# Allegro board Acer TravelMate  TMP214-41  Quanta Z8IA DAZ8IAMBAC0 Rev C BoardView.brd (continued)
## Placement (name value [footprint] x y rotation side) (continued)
PR8001  20K_1%_2  [R0201]  53.11 200.28 180 top
PR8002  220K_1%_2  [R0201]  56.84 196.9 180 top
PR8003  20K_1%_2  [R0201]  33.45 102 180 top
PR8004  220K_1%_2  [R0201]  36.06 101.6 90 top
PR8005  10K_1%_2  [R0201]  53.34 198.4 0 top
PR8006  200K_1%_2  [R0201]  34.61 97.29 270 top
PR8007  10K_1%_2  [R0201]  34.69 102 0 top
PR8008  220K_1%_2  [R0201]  55.72 196.9 180 top
PR8009  110K_1%_2  [R0201]  37.22 101.61 270 top
PR8010  *Short_0201  [S0201]  51.56 196.67 180 top
PR8011  *0_5%_4  [R0402]  53.34 197.35 0 top
PR8012  100K_1%_2  [R0201]  48.81 199.06 270 top
PR8013  *Short_0201  [S0201]  48.79 197.33 270 top
PR8014  *Short_0201  [S0201]  33.23 97.66 180 top
PR8015  *Short_0201  [S0201]  39.96 100.3 90 top
PR8016  300K_1%_2  [R0201]  35.67 97.33 270 top
PR8017  100K_1%_2  [R0201]  38.99 100.33 90 top
PR8018  549K_1%_4  [R0402]  56.99 195.91 0 top
PR8019  *0_5%_4  [R0402]  55.24 195.91 180 top
PR8020  *Short_0201  [S0201]  53.51 195.91 0 top
PR8021  76.8K_1%_4  [R0402]  57.35 194.56 90 top
PR8022  47K_1%_2  [R0201]  36.7 119.83 90 top
PR8023  470K_1%_2  [R0201]  81.2 187.58 0 top
PR8024  47K_1%_2  [R0201]  88.79 190.75 90 top
PR8025  *1M_5%_4  [R0402]  59.35 193.19 270 top
PR8026  *Short_0201  [S0201]  58.31 192.99 270 top
PR8027  33K_1%_4  [R0402]  58.36 194.61 270 top
PR8028  220K_1%_2  [R0201]  51.2 191.59 180 top
PR8029  100K_1%_2  [R0201]  57.3 192.96 270 top
PR8030  100K_1%_2  [R0201]  83.76 190.27 270 top
PR8031  470K_1%_2  [R0201]  37.74 119.83 90 top
PR8032  470K_1%_2  [R0201]  89.76 190.24 90 top
PR8033  *Short_0402  [S0402]  25.07 116.76 90 top
PR8034  *Short_0402  [S0402]  17.34 113.77 90 top
PR8035  10K_1%_2  [R0201]  24.51 118.08 180 top
PR8036  18.7K_1%_4  [R0402]  16.98 117.34 90 top
PR8037  *0_5%_4  [R0402]  18.36 113.75 90 top
PR8038  *10K_1%_2  [R0201]  31.77 116.56 90 top
PR8039  10K_1%_4  [R0402]  18.12 118.84 270 top
PR8040  10K_1%_2  [R0201]  23.52 118.08 0 top
PR8041  *Short_0201  [S0201]  31.85 115.08 180 top
PR8042  1M_1%_2  [R0201]  26.16 113.81 0 top
PR8043  1M_1%_2  [R0201]  31.77 117.57 90 top
PR8044  510K_5%_2  [R0201]  22.83 115.47 270 top
PR8045  220K_5%_2  [R0201]  24.38 112.57 180 top
PR8046  1K_1%_2  [R0201]  26.79 116.4 0 top
PR8047  220K_5%_2  [R0201]  26.16 112.57 0 top
PR8048  *1K_1%_2  [R0201]  26.13 115.47 270 top
PR8049  *0_5%_4  [R0402]  28.37 106.45 90 top
PR8050  *0_5%_4  [R0402]  30.88 106.07 270 top
PR8051  *0_5%_4  [R0402]  31.37 107.42 0 top
PR8052  *0_5%_4  [R0402]  36.24 114.32 180 top
PR8053  *27.4K_1%_4  [R0402]  32.14 109.92 90 top
PR8054  *10K_1%_2  [R0201]  33.88 114.2 0 top
PR8055  *10.2K_1%_4  [R0402]  33.14 108.49 270 top
PR8056  *1M_1%_2  [R0201]  24.99 111.55 90 top
PR8057  *10K_1%_2  [R0201]  34.87 114.2 0 top
PR8058  *10K_1%_2  [R0201]  19.86 111.99 270 top
PR8059  *1M_1%_2  [R0201]  27.53 108.56 270 top
PR8060  *0_5%_4  [R0402]  18.56 111.96 0 top
PR8061  *220K_5%_2  [R0201]  27.98 111.97 270 top
PR8062  *220K_5%_2  [R0201]  24.99 110.54 270 top
PR8063  *1K_1%_2  [R0201]  24.84 109.52 180 top
PR8064  *1M_1%_2  [R0201]  19.86 110.99 270 top
PR9000  EV@1_5%_6  [R0603]  94.99 193.37 90 top
PR9001  EV@1_5%_6  [R0603]  105.58 200.05 135 top
PR9002  EV@499K_1%_4  [R0402]  98.57 194.05 0 top
PR9004  *EV@2.2_5%_6  [R0603]  105.61 202.92 315 bottom
PR9006  EV@1_5%_6  [R0603]  98.29 199.06 0 bottom
PR9008  *Short_0201  [S0201]  104.95 194.1 180 top
PR9009  EV@10K_1%_2  [R0201]  104.95 193.39 180 top
PR9011  EV@14.7K_1%_4  [R0402]  102.44 198.05 45 bottom
PR9013  EV@10K_1%_4  [R0402]  104.85 193.49 270 bottom
PR9014  EV@1_5%_6  [R0603]  114.09 191.59 90 bottom
PR9015  *Short_0201  [S0201]  97.79 197.41 0 top
PR9016  *Short_0402  [S0402]  97.06 199.12 180 top
PR9017  *Short_0201  [S0201]  98.67 197.52 270 top
PR9018  *EV@12K_1%_4  [R0402]  97.06 200.08 180 top
PR9019  *EV@2.2_5%_6  [R0603]  105.86 197.48 270 bottom
PR9021  EV@20.5K_1%_4  [R0402]  98.06 194.92 270 bottom
PR9022  *EV@10K_1%_4  [R0402]  98.5 198.9 90 top
PR9023  EV@6.19K_1%_4  [R0402]  97.86 196.55 180 top
PR9024  EV@4.32K_1%_4  [R0402]  96.06 196.54 0 top
PR9025  *EV@0_5%_2  [R0201]  102.66 193.9 45 bottom
PR9026  EV@100_1%_4  [R0402]  116.76 190.4 90 bottom
PR9027  EV@16.5K_1%_4  [R0402]  95.32 195.53 0 top
PR9028  *Short_0201  [S0201]  99.65 191.48 180 top
PR9029  *Short_0201  [S0201]  98.7 192.2 180 top
PR9030  EV@309_1%_4  [R0402]  93.95 195.84 90 top
PR9031  EV@100_1%_4  [R0402]  115.77 190.4 90 bottom
PR9032  EV@14.7K_1%_4  [R0402]  100.88 194.71 45 bottom
PR9033  EV@10K_1%_2  [R0201]  103.42 192.76 315 top
PR9034  *Short_0201  [S0201]  103.17 197.51 225 bottom
PR9067  *Short_0805  [S0805]  97.56 186.08 270 bottom
PR9068  *Short_0805  [S0805]  96.65 183.28 0 bottom
PR9069  *Short_0402  [S0402]  88.69 185.49 270 top
PR9070  EV@0_5%_2  [R0201]  89.45 182.78 180 top
PR9072  EV@0_5%_2  [R0201]  90.06 185.72 0 top
PR9073  EV@5.6_5%_8  [R0805]  95.55 192 180 bottom
PR9074  EV@100K_1%_4  [R0402]  104.95 191.56 90 bottom
PR9075  EV@10K_1%_4  [R0402]  104.56 187.67 0 bottom
PR9076  EV@10K_1%_2  [R0201]  106.34 183.79 0 bottom
PR9077  EV@1M_5%_4  [R0402]  103.93 191.56 270 bottom
PR9078  EV@0_5%_2  [R0201]  105.2 183.79 180 bottom
PR9079  EV@0_5%_2  [R0201]  100.17 181.61 180 bottom
PR9080  EV@47_1%_4  [R0402]  101.09 186.7 180 bottom
PR9081  EV@133_1%_4  [R0402]  99.72 186.97 90 bottom
PR9082  EV@124_1%_4  [R0402]  99.31 184.55 270 bottom
PR9085  *Short_0402  [S0402]  99.35 194.97 90 bottom
PR9086  EV@100K_1%_4  [R0402]  168.56 151.32 0 bottom
PR9087  EV@10_5%_6  [R0603]  168.04 158.17 0 bottom
PR9088  EV@100K_1%_2  [R0201]  168.07 157.68 270 top
PR9089  EV@2.2_5%_6  [R0603]  166.01 158.81 90 bottom
PR9090  EV@0_5%_2  [R0201]  168.19 155.72 270 top
PR9091  *EV@0_5%_2  [R0201]  168.95 156.62 90 top
PR9092  *EV@4.7_5%_6  [R0603]  162.29 158.29 180 top
PR9093  EV@0_5%_2  [R0201]  169.21 155.75 180 top
PR9094  EV@6.49K_1%_4  [R0402]  170.91 151.3 270 bottom
PR9095  EV@2.2K_5%_4  [R0402]  169.41 155.3 180 bottom
PR9096  *EV@0_5%_4  [R0402]  170.28 153.09 0 bottom
PR9097  EV@9.31K_1%_4  [R0402]  168.94 152.7 270 bottom
PR9098  EV@0_5%_4  [R0402]  170.28 153.08 180 top
PR9099  EV@22_5%_8  [R0805]  165.82 168.16 90 top
PR9100  EV@100K_1%_4  [R0402]  160.6 168.55 180 top
PR9101  EV@1M_5%_4  [R0402]  160.98 167.1 90 top
PR9102  EV@1M_5%_6  [R0603]  155.15 168.25 180 top
PR9103  EV@22_5%_8  [R0805]  164.64 209.6 180 top
PR9104  EV@1M_5%_6  [R0603]  155.91 170.35 270 top
PR9105  *EV@100K_1%_6  [R0603]  158.96 209.94 90 top
PR9227  22_5%_8  [R0805]  37.38 125.12 0 top
PR9244  *Short_0805  [S0805]  206.15 126.2 180 bottom
PR9245  *Short_0805  [S0805]  209.67 129.34 0 bottom
PR9248  *Short_0805  [S0805]  37.52 158.86 90 top
PR9249  *Short_0805  [S0805]  32.68 158.77 180 top
PR9255  100K_1%_2  [R0201]  36.62 145.56 0 top
PR9256  *Short_0201  [S0201]  38.1 145.56 270 top
PR9263  *Short_0201  [S0201]  167.56 166.67 0 top
PR9268  *0_5%_2  [R0201]  169.72 135.02 270 bottom
PR9269  *0_5%_2  [R0201]  170.48 135.02 270 bottom
PR9270  *0_5%_2  [R0201]  60.88 182.9 90 bottom
PR9271  *0_5%_2  [R0201]  60.88 183.92 270 bottom
PR9274  *EV@100K_NTC_4_1%  [R0402]  107.54 202.46 90 bottom
PR9275  *Short_0201  [S0201]  163.37 121.18 90 top
PR9276  *Short_0201  [S0201]  160.57 123.03 180 top
PR9277  *0_5%_4  [R0402]  39.37 101.7 0 top
PR9278  *Short_0201  [S0201]  84.25 188.95 180 top
PR9279  *Short_0201  [S0201]  39.09 120.34 180 top
PR9280  *Short_0201  [S0201]  69.41 205.25 90 top
PR9281  *Short_0201  [S0201]  36.14 115.82 270 top
PR9284  *EV@1K_1%_4  [R0402]  99.11 193.19 90 bottom
PR9285  *Short_0201  [S0201]  168.96 135.02 90 bottom
PR9286  22_5%_8  [R0805]  26.08 139.47 0 top
PR9287  *Short_0201  [S0201]  60.12 183.92 90 bottom
PR9288  *Short_0603  [S0603]  87.04 172.36 180 top
PR9289  *100K_1%_2  [R0201]  165.35 149.65 90 bottom
PU1  BQ24780SRUYR  [QFN28-4X4-4-38P]  158.79 119.35 0 bottom
PU3002  TMP708AIDBVR  [SOT23-2_8-95-5P-LP2985-50DBVT]  131.33 116.55 90 bottom
PU3003  *JW5222RSOTB_TRPBF  [SOT23-2_8-95-6P-1_1H]  6.17 34.44 0 bottom
PU3004  JW5213DFND_TRPBF  [DFN8-2X2-5-9P-MAX8902B]  36.75 140.74 180 top
PU5000  G5719CTB1U  [SOT23-6-2_8-95-6P-G5126TB1U]  72.33 186.61 0 bottom
PU5001  RT8231BGQW  [WQFN20-3X3-4-21P]  90.39 176.09 0 top
PU6000  RT6256BGQUF  [QFN12-3X3-45-0_6H]  177.21 130.65 0 bottom
PU6001  AOZ1331ADI  [DFN14-3X2-4-11P-0_8H]  201.13 128.93 90 bottom
PU6002  AOZ1331ADI  [DFN14-3X2-4-11P-0_8H]  35.48 163.34 180 top
PU6003  RT6258CGQUF  [QFN12-3X3-45-0_6H]  55.67 183.08 180 bottom
PU7000  RT3612EBGQW  [QFN32-4X4-4-33P-RT8845B]  159.96 145.87 315 bottom
PU7001  RT6543AGQW  [QFN20-3X3-4-21P-RT6543B]  162.99 134.31 270 bottom
PU8000  AP2204K-ADJTRG1  [SOT23-2_825-95-5P]  20.82 117.7 0 top
PU8001  *AP2204K-ADJTRG1  [SOT23-2_825-95-5P]  35.4 110.66 90 top
PU9000  EV@RT8813DGQW  [QFN24-4X4-5-25P-RT8813D]  101.99 195.99 225 top
PU9002  EV@AOZ1331ADI  [DFN14-3X2-4-11P-0_8H]  94.41 184.17 270 top
PU9003  EV@G9336ADJTP1U  [TSOT23-6-2_8-95-6P-1H]  102.36 184.57 0 bottom
PU9004  EV@G5335QT2U  [QFN23-4X4-5-25P]  165.53 154.41 270 bottom
PU9005  *M74VHC1GT08DFT2G  [SC70-2_1-65-5P]  31.92 140.1 90 top
PU9006  *MC74VHC1G08DFT2G  [SOT353-1-2_125-65-5P]  166.75 147.67 270 bottom
Q9  EV@PJA138K  [SOT23-2-95-3P]  112.31 188.41 90 bottom
Q13  EV@PJX138K  [SOT563-1_6-5-6P-PJX138K]  134.79 175.92 0 bottom
Q14  EV@DMG1012T-7  [SOT23-1_38-5-3P]  110.87 186.36 90 top
Q15  *EV@DMG1012T-7  [SOT23-1_38-5-3P]  106.17 182.22 180 bottom
Q16  EV@DMG1012T-7  [SOT23-1_38-5-3P]  112.19 188.87 180 top
Q20  EV@DMG1012T-7  [SOT23-1_38-5-3P]  162.2 190.5 0 top
Q21  *PJA138K  [SOT23-2-95-3P]  32.81 29.08 180 bottom
Q22  2N7002KTB  [SOT23-1_38-5-3P]  78.91 102.89 180 top
Q23  DMP2130L-7  [SOT23-2-95-3P]  29.63 175.3 270 top
Q28  METR3904-G  [SOT23-2-95-3P]  5.12 12.46 180 top
Q30  DMP2130L-7  [SOT23-2-95-3P]  216.48 122.32 180 bottom
Q31  DDTC144EUA-7-F  [SOT23-1_7-65-3P]  214.17 119.4 270 bottom
Q32  DMP2130L-7  [SOT23-2-95-3P]  114.32 107.87 90 bottom
Q33  *2N7002KTB  [SOT23-1_38-5-3P]  185.59 111.91 0 top
Q62  SSM6N43FU  [SC70-2_1-65-6P]  25.45 135.66 0 top
Q63  2N7002KTB  [SOT23-1_38-5-3P]  185.59 109.37 90 top
Q81  PJA138K  [SOT23-2-95-3P]  13.63 147.34 0 bottom
Q85  DMG301NU-7  [SOT23-2-95-3P]  109.39 107.21 180 top
Q86  METR3904-G  [SOT23-2-95-3P]  105.46 104.26 180 top
Q124  *METR3904-G  [SOT23-2-95-3P]  54.83 136.88 0 top
Q6508  G5250Q1T73U  [SOT23-2_38-95-3P]  17.04 134.18 180 top
Q6509  2N7002K  [SOT23-2-95-3P]  142.29 96.75 90 top
Q6512  EV@2N7002KTB  [SOT23-1_38-5-3P]  130.98 176.04 270 bottom
Q6520  *2N7002KTB  [SOT23-1_38-5-3P]  78.79 106.07 270 top
Q6521  2N7002KDW  [SOT363-2_1-65-6P]  86.52 189.22 0 bottom
Q6522  DDTC144EUA-7-F  [SOT23-1_7-65-3P]  81.83 190.14 270 bottom
Q6523  METR3904-G  [SOT23-2-95-3P]  164.41 123.59 180 bottom
Q6531  2N7002K  [SOT23-2-95-3P]  25.7 159.79 270 top
Q6534  CRT@G5250Q1T73U  [SOT23-2_38-95-3P]  19.03 150.29 180 top
Q6540  SPIN_EXT@2N7002K  [SOT23-2-95-3P]  131.86 213.36 90 top
Q6544  METR3904-G  [SOT23-2-95-3P]  140.83 159.7 180 top
Q6554  I219@2N7002KDW  [SOT363-2_1-65-6P]  11.6 167.28 0 top
Q6555  NFC@2N7002KTB  [SOT23-1_38-5-3P]  59.66 94.51 90 top
Q6556  NFC@2N7002KTB  [SOT23-1_38-5-3P]  64.31 94.51 90 top
Q6557  NFC@2N7002KTB  [SOT23-1_38-5-3P]  66.59 94.51 90 top
Q6558  NFC@2N7002KTB  [SOT23-1_38-5-3P]  69.9 94.38 90 top
Q6559  NFC@2N7002KTB  [SOT23-1_38-5-3P]  61.87 94.64 270 top
Q6564  2N7002KDW  [SOT363-2_1-65-6P]  93.77 182.65 270 bottom
Q6565  2N7002K  [SOT23-2-95-3P]  30.68 52.3 270 bottom
Q6567  **SPIN_INT@2N7002KDW  [SOT363-2_1-65-6P]  150.79 215.8 0 top
Q6570  2N7002K  [SOT23-2-95-3P]  32.68 56.92 270 bottom
Q6582  METR3904-G  [SOT23-2-95-3P]  83.1 169.95 270 top
Q6583  2N7002KTB  [SOT23-1_38-5-3P]  87.17 169.06 270 top
Q6585  *2N7002KDW  [SOT363-2_1-65-6P]  77.9 119.78 90 top
Q6588  2N7002KTB  [SOT23-1_38-5-3P]  91.96 107.08 180 top
Q6589  METR3904-G  [SOT23-2-95-3P]  88.97 107.59 180 top
Q6591  TSN@DMP2130L-7  [SOT23-2-95-3P]  74.72 186.59 0 top
Q6592  TSN@DDTC144EUA-7-F  [SOT23-1_7-65-3P]  77.9 187.55 0 top
Q6593  2N7002K  [SOT23-2-95-3P]  6.12 42.57 90 bottom
Q6597  *2N7002KDW  [SOT363-2_1-65-6P]  161.08 140.36 270 top
Q6598  *2N7002KDW  [SOT363-2_1-65-6P]  163.55 140.36 270 top
Q6600  *DMP2130L-7  [SOT23-2-95-3P]  200.58 116.1 0 bottom
Q6601  **2N7002KDW  [SOT363-2_1-65-6P]  205.02 118.13 180 bottom
Q6602  2N7002KTB  [SOT23-1_38-5-3P]  14.27 59.33 90 bottom
Q6603  2N7002KTB  [SOT23-1_38-5-3P]  26.59 47.7 0 bottom
Q6604  SM@DMP2130L-7  [SOT23-2-95-3P]  228.39 93.75 0 top
Q6605  SM@DDTC144EUA-7-F  [SOT23-1_7-65-3P]  234.49 95.91 90 top
Q6606  *EX-IO@2N7002KDW  [SOT363-2_1-65-6P]  137.33 128.6 0 bottom
Q6607  DMG3414U-7  [SOT23-2-95-3P]  209.21 121.31 270 bottom
Q6608  2N7002KDW  [SOT363-2_1-65-6P]  202.36 120.8 90 top
Q6609  EMF11N02J  [SOT23-2_38-95-3P]  169.08 139.85 180 bottom
Q6610  2N7002K  [SOT23-2-95-3P]  170.48 148.74 90 bottom
Q6611  DDTC144EUA-7-F  [SOT23-1_7-65-3P]  170.48 150.9 270 top
Q6612  *PJA138K  [SOT23-2-95-3P]  18.84 73.94 0 top
Q6616  *2N7002KDW  [SOT363-2_1-65-6P]  73.71 94 0 top
Q6617  2N7002K  [SOT23-2-95-3P]  8.2 56.79 0 bottom
Q6618  2N7002K  [SOT23-2-95-3P]  29.13 160.8 0 top
Q6619  I219@2N7002K  [SOT23-2-95-3P]  31.92 165.63 180 top
Q6620  2N7002K  [SOT23-2-95-3P]  11.35 163.22 0 top
Q6621  *2N7002KTB  [SOT23-1_38-5-3P]  10 43.08 270 bottom
Q6622  2N7002KTB  [SOT23-1_38-5-3P]  26.59 54.51 0 bottom
Q6623  *2N7002KTB  [SOT23-1_38-5-3P]  10 45.62 270 bottom
Q6624  2N7002KTB  [SOT23-1_38-5-3P]  26.59 52.22 0 bottom
Q6625  2N7002KTB  [SOT23-1_38-5-3P]  26.59 49.93 0 bottom
Q6626  *2N7002KTB  [SOT23-1_38-5-3P]  20.77 42.01 180 bottom
Q6627  *2N7002KTB  [SOT23-1_38-5-3P]  18.41 41.65 270 bottom
Q6628  *2N7002KTB  [SOT23-1_38-5-3P]  16.17 41.07 270 bottom
Q6629  *2N7002KTB  [SOT23-1_38-5-3P]  13.97 41.07 270 bottom
Q6631  SPIN_EXT@2N7002KDW  [SOT363-2_1-65-6P]  147.87 210.72 270 bottom
Q6632  SPIN_EXT@2N7002K  [SOT23-2-95-3P]  102.66 181 270 bottom
Q6633  SPIN_EXT@2N7002K  [SOT23-2-95-3P]  106.09 178.3 270 bottom
Q6637  **SPIN_INT@2N7002K  [SOT23-2-95-3P]  144.83 210.59 0 top
Q6638  *SPIN_INT@2N7002KDW  [SOT363-2_1-65-6P]  126.41 113.31 270 bottom
Q6639  *METR3904-G  [SOT23-2-95-3P]  53.39 140.36 90 top
Q6640  *METR3904-G  [SOT23-2-95-3P]  91.79 178.74 270 bottom
Q6642  *HDD_MS@AO3413  [SOT23-2_38-95-3P]  233.34 123.21 90 top
Q6643  *HDD_MS@2N7002K  [SOT23-2-95-3P]  229.66 125.5 90 top
Q6644  *HDD_MS@AO3413  [SOT23-2_38-95-3P]  216.2 107.72 270 top
Q6645  *HDD_MS@2N7002K  [SOT23-2-95-3P]  213.41 104.54 270 top
Q6646  *2N7002K  [SOT23-2-95-3P]  59.69 175.16 90 top
Q6649  2N7002KTB  [SOT23-1_38-5-3P]  105.96 109.5 180 bottom
Q6651  PJX138K  [SOT563-1_6-5-6P-PJX138K]  138.48 98.96 90 top
Q6652  EV@2N7002KTB  [SOT23-1_38-5-3P]  116.05 180.69 180 top
Q6653  **SPIN_INT@2N7002K  [SOT23-2-95-3P]  51.23 195.09 270 bottom
Q6654  PJA138K  [SOT23-2-95-3P]  88.62 126.34 180 top
Q6655  *SSD_MS@AO3413  [SOT23-2_38-95-3P]  20.65 77.37 90 top
Q6656  *SSD_MS@2N7002K  [SOT23-2-95-3P]  24.43 81.68 90 top
Q6657  *DDTC144EUA-7-F  [SOT23-1_7-65-3P]  63.11 175 0 top
QG15  EV@DMG1012T-7  [SOT23-1_38-5-3P]  111.45 179.24 270 bottom
QG17  *EV@PJX138K  [SOT563-1_6-5-6P-PJX138K]  113.03 176.83 90 bottom
R36  4.7K_1%_2  [R0201]  92.25 120.67 180 top
R61  *CRT@0_4/S  [S0402]  35.61 146.45 270 top
R101  4.7K_1%_2  [R0201]  138.35 100.48 0 top
R224  240_1%_2  [R0201]  46.4 137.44 270 top
R225  *0_5%_4  [R0402]  45.13 108.23 180 top
R226  *0_5%_4  [R0402]  45.13 106.19 180 top
R227  *0_5%_4  [R0402]  44.67 128.11 180 top
R228  *0_4/S  [S0402]  45.13 107.21 0 top
R229  *0_4/S  [S0402]  45.13 105.18 180 top
R230  *0_4/S  [S0402]  45.01 129.48 270 top
R231  240_1%_2  [R0201]  49.91 148.48 180 top
R232  240_1%_2  [R0201]  49.92 147.74 180 top
R233  *240_1%_2  [R0201]  47.18 149.02 180 top
R234  *240_1%_2  [R0201]  49.9 149.97 0 top
R235  *240_1%_2  [R0201]  52.3 147.25 180 top
R236  *240_1%_2  [R0201]  52.35 145.85 180 top
R237  *240_1%_2  [R0201]  47.29 149.78 180 top
R238  *240_1%_2  [R0201]  49.92 149.22 0 top
R239  *240_1%_2  [R0201]  47.72 146.79 180 top
R240  *240_1%_2  [R0201]  47.85 145.97 180 top
R241  1K_1%_2  [R0201]  45.98 124.37 180 top
R242  2_1%_6  [R0603]  45.25 121.87 270 top
R243  1K_1%_2  [R0201]  46.02 126.05 0 top
R244  24.9_1%_2  [R0201]  45.51 118.26 180 top
R296  *EV@0_4/S  [S0402]  120.19 207.92 180 bottom
R297  EV@10K_1%_2  [R0201]  115.54 188.36 270 bottom
R299  *EV@0_4/S  [S0402]  126.81 198.36 90 top
R305  *EV@0_4/S  [S0402]  110.76 185.54 90 bottom
R306  EV@100K_1%_2  [R0201]  110.51 186.81 0 bottom
R307  *EV@200_1%_2  [R0201]  141.24 207.26 180 bottom
R310  4.7K_1%_2  [R0201]  7.51 13.51 180 top
R311  EV@10K_1%_2  [R0201]  121.84 208.81 90 bottom
R312  EV@2.49K_1%_2  [R0201]  142.9 207.11 180 bottom
R313  EV@10K_1%_2  [R0201]  116.07 187.4 180 bottom
R314  EV@10K_1%_2  [R0201]  145.08 189.76 90 bottom
R315  EV@10K_1%_2  [R0201]  145.59 188.49 180 bottom
R316  EV@10K_1%_2  [R0201]  146.22 187.47 180 bottom
R317  EV@10K_1%_2  [R0201]  159.81 204.49 0 top
R318  EV@40.2_1%_2  [R0201]  146.98 181.76 180 top
R319  EV@40.2_1%_2  [R0201]  146.41 182.97 270 top
R320  EV@60.4_1%_2  [R0201]  146.47 183.51 0 bottom
R321  *EV@60.4_1%_2  [R0201]  136.41 186.63 0 top
R322  *EV@60.4_1%_2  [R0201]  136.75 189.43 270 top
R323  *EV@0_5%_4  [R0402]  124.92 208.77 180 bottom
R324  *EV@0_4/S  [S0402]  124.92 209.78 180 bottom
R325  EV@100K_1%_2  [R0201]  128.06 208.68 90 bottom
R326  EV@10K_1%_2  [R0201]  118.46 177.64 270 bottom
R329  *EV@0_4/S  [S0402]  124.67 192.21 270 top
R330  *EV@10K_1%_2  [R0201]  123.49 176.43 270 bottom
R331  EV@10K_1%_2  [R0201]  124.89 178.46 270 bottom
R332  EV@10K_1%_2  [R0201]  124.12 178.46 270 bottom
R338  100K_1%_2  [R0201]  91.84 122.22 270 top
R339  *EV@0_4/S  [S0402]  134.41 178.33 0 bottom
R341  EV@100K_1%_2  [R0201]  131.85 177.8 270 bottom
R342  EV@100K_1%_2  [R0201]  130.3 178.18 270 bottom
R343  EV@100K_1%_2  [R0201]  132.89 178.33 0 bottom
R344  XX@100K_1%_2  [R0201]  114.22 185.95 180 bottom
R345  XX@100K_1%_2  [R0201]  114.22 184.93 180 bottom
R346  XX@100K_1%_2  [R0201]  114.22 183.16 180 bottom
R347  *EV@100K_1%_2  [R0201]  114.22 186.79 180 bottom
R348  *EV@100K_1%_2  [R0201]  114.22 182.39 180 bottom
R349  *EV@100K_1%_2  [R0201]  114.12 183.92 180 bottom
R350  *EV@30.1K_1%_4  [R0402]  131.46 179.19 0 bottom
R351  *EV@100K_1%_2  [R0201]  132.89 179.22 0 bottom
R352  EV@100K_1%_2  [R0201]  129.43 178.46 0 bottom
R353  XX@100K_1%_2  [R0201]  116.5 185.57 0 bottom
R354  XX@100K_1%_2  [R0201]  116.5 184.43 180 bottom
R355  XX@100K_1%_2  [R0201]  116.5 182.65 0 bottom
R356  EV@100K_1%_2  [R0201]  116.5 186.59 0 bottom
R357  EV@100K_1%_2  [R0201]  116.5 181.89 0 bottom
R358  EV@100K_1%_2  [R0201]  116.5 183.54 0 bottom
R359  *0_5%_4  [R0402]  169.34 114.83 0 top
R361  4.7K_1%_2  [R0201]  162 113.18 90 top
R362  EV@4.7K_1%_2  [R0201]  137.21 175.44 180 bottom
R363  EV@2.2K_5%_2  [R0201]  123.16 178.46 270 bottom
R364  *EV@0_4/S  [S0402]  122.6 176.43 90 bottom
R365  EV@4.7K_1%_2  [R0201]  132.5 175.31 270 bottom
R366  EV@2.2K_5%_2  [R0201]  122.35 178.46 270 bottom
R367  EV@2.2K_5%_2  [R0201]  121.58 178.46 270 bottom
R368  EV@2.2K_5%_2  [R0201]  120.82 178.46 270 bottom
R369  4.7K_1%_2  [R0201]  161.26 113.18 90 top
R370  *EV@0_4/S  [S0402]  116.25 179.73 0 bottom
R372  *EV@0_4/S  [S0402]  114.53 186.89 270 top
R373  *EV@0_4/S  [S0402]  115.23 184.68 0 top
R374  *EV@0_4/S  [S0402]  116.17 183.03 0 top
R376  *EV@0_4/S  [S0402]  116.25 180.74 0 bottom
R378  *EV@10K_1%_2  [R0201]  129.51 176.55 90 bottom
R380  43_5%_2  [R0201]  159.3 114.7 0 top
R382  *EV@0_5%_4  [R0402]  105.84 180.62 180 bottom
R383  4.7K_1%_2  [R0201]  146.98 109.62 0 top
R384  *EV@0_4/S  [S0402]  108 180.87 0 bottom
R385  *EV@4.7K_1%_2  [R0201]  108.76 182.27 0 bottom
R386  EV@10K_1%_2  [R0201]  113.33 187.35 0 top
R391  EV@10K_1%_2  [R0201]  113.96 180.87 180 bottom
R394  EV@10K_1%_2  [R0201]  115.11 188.36 0 top
R395  EV@10K_1%_2  [R0201]  116.84 178.71 270 bottom
R396  EV@10K_1%_2  [R0201]  115.57 205.89 180 bottom
R397  EV@10K_1%_2  [R0201]  114.35 183.28 180 top
R398  EV@100K_1%_2  [R0201]  124.69 187.15 270 top
R399  *EV@10K_1%_2  [R0201]  113.96 179.85 180 bottom
R402  *22_5%_2  [R0201]  149.6 104.85 0 top
R403  EV@10K_1%_2  [R0201]  114.22 182.39 270 top
R404  EV@10K_1%_2  [R0201]  114.22 181.63 180 bottom
R405  EV@120_1%_2  [R0201]  158.77 187.07 270 bottom
R406  EV@120_1%_2  [R0201]  158.39 191.77 0 bottom
R407  EV@549_1%_2  [R0201]  159.91 189.48 180 top
R409  100K_1%_2  [R0201]  79.04 104.42 180 top
R410  EV@1.33K_1%_2  [R0201]  159.91 188.46 0 top
R411  EV@931_1%_2  [R0201]  159.91 190.5 0 top
R414  20K_1%_2  [R0201]  24.3 97.81 90 top
R415  39K_1%_2  [R0201]  22.4 97.05 90 top
R416  100K_1%_2  [R0201]  18.44 100.96 90 top
R417  10K_1%_2  [R0201]  16.1 97.3 270 top
R418  10K_1%_2  [R0201]  16.35 99.01 0 top
R421  *0_4/S  [S0402]  20.49 89.81 180 top
R422  *0_4/S  [S0402]  20.51 90.82 180 top
R424  *0_4/S  [S0402]  23.21 91.21 90 top
R425  *0_4/S  [S0402]  19.63 103.4 180 top
R426  *0_4/S  [S0402]  19.63 104.42 180 top
R427  *0_4/S  [S0402]  22.94 105.2 180 top
R428  *0_4/S  [S0402]  22.94 106.4 180 top
R429  *0_4/S  [S0402]  24.23 107.36 180 top
R430  *0_4/S  [S0402]  24.23 108.56 180 top
R432  *0_4/S  [S0402]  24.18 91.21 90 top
R436  *0_4/S  [S0402]  69.96 188.7 180 bottom
R439  *1K_1%_2  [R0201]  64.56 188.24 270 bottom
R440  *1K_1%_2  [R0201]  83.48 192.15 270 bottom
R441  1K_1%_2  [R0201]  66.34 188.24 90 bottom
R442  100K_1%_2  [R0201]  67.61 188.49 90 bottom
R443  10_5%_2  [R0201]  65.58 188.24 270 bottom
R445  *0_4/S  [S0402]  78.48 194.72 180 top
R446  100K_1%_2  [R0201]  78.48 193.67 90 top
R447  100K_1%_2  [R0201]  16.68 27.58 90 top
R449  *0_5%_4  [R0402]  12.62 37.66 180 bottom
R450  *0_6/S  [S0603]  18.82 25.54 90 bottom
R451  200K_1%_2  [R0201]  23.03 27.58 270 bottom
R452  100K_1%_2  [R0201]  24.3 27.71 0 bottom
R454  *0_5%_4  [R0402]  24.68 37.23 90 bottom
R455  *Short_0603  [S0603]  26.59 37.13 0 bottom
R458  *CRT@4.7K_1%_2  [R0201]  31.8 148.1 90 top
R459  *0_4/S  [S0402]  28.49 36.34 270 bottom
R460  *0_5%_4  [R0402]  28.11 28.22 90 bottom
R461  22_5%_2  [R0201]  26.23 34 180 bottom
R462  *Short_0603  [S0603]  29.33 28.06 90 bottom
R463  *0_4/S  [S0402]  13.13 36.47 180 bottom
R464  *0_5%_4  [R0402]  19.09 18.81 135 bottom
R465  *0_5%_4  [R0402]  21.51 21.04 135 top
R467  *0_4/S  [S0402]  13.13 33.55 180 bottom
R468  2.2K_5%_2  [R0201]  19.63 25.12 90 top
R469  *0_5%_4  [R0402]  18 38.63 270 bottom
R470  *0_4/S  [S0402]  19.09 18.81 315 top
R471  2.2K_5%_2  [R0201]  20.37 25.12 90 top
R472  62_1%_2  [R0201]  15.77 21.56 0 bottom
R473  62_1%_2  [R0201]  10.78 28.48 90 bottom
R474  *10K_1%_2  [R0201]  17.14 21.21 270 bottom
R475  *10K_1%_2  [R0201]  18.16 22.14 270 bottom
R476  4.7K_1%_2  [R0201]  17.01 22.62 270 bottom
R477  4.7K_1%_2  [R0201]  18.29 23.39 180 bottom
R478  1K_1%_2  [R0201]  23.1 37.1 90 bottom
R479  *10K_1%_2  [R0201]  30.4 34.06 90 bottom
R490  2.2K_5%_2  [R0201]  16.17 131.21 270 top
R491  2.2K_5%_2  [R0201]  16.17 130.07 90 top
R495  *HDD@4.7K_1%_2  [R0201]  235.38 115.85 0 top
R497  HDD@4.7K_1%_2  [R0201]  233.85 115.08 180 top
R498  *HDD@4.7K_1%_2  [R0201]  235.38 115.08 0 top
R499  *HDD@4.7K_1%_2  [R0201]  233.85 114.27 180 top
R500  HDD@4.7K_1%_2  [R0201]  235.38 114.27 0 top
R503  *HDD@4.7K_1%_2  [R0201]  225.17 114.8 180 top
R504  HDD@4.7K_1%_2  [R0201]  226.69 115.74 0 top
R505  *HDD@4.7K_1%_2  [R0201]  225.17 115.74 180 top
R506  *HDD@4.7K_1%_2  [R0201]  226.69 117.67 0 top
R509  8111K@1K_1%_2  [R0201]  29 157.91 180 top
R510  8111K@15K_1%_2  [R0201]  23.67 161.57 0 top
R511  *0_4/S  [S0402]  29.38 169.06 180 top
R512  *0_4/S  [S0402]  29.38 170.08 180 top
R516  75_1%_8  [R0805]  38.15 184.81 270 top
R517  75_1%_8  [R0805]  35.86 184.81 270 top
R518  75_1%_8  [R0805]  32.56 184.81 270 top
R519  75_1%_8  [R0805]  30.27 184.81 270 top
R558  *0_4/S  [S0402]  127.68 99.72 180 top
R560  *0_4/S  [S0402]  129.59 99.72 0 top
R566  4.7K_1%_2  [R0201]  135.3 97.43 90 top
R567  4.7K_1%_2  [R0201]  130.31 96.19 180 top
R572  *0_4/S  [S0402]  126.24 96.65 90 top
R573  *0_4/S  [S0402]  133.45 103.2 0 bottom
R574  *10K_1%_2  [R0201]  127.25 96.65 90 top
R575  *Short_0603  [S0603]  171.23 111.5 180 bottom
R576  1K_1%_2  [R0201]  166 124.71 90 bottom
R579  10K_1%_2  [R0201]  214.17 121.64 270 bottom
R580  10K_1%_2  [R0201]  83.87 99.72 270 top
R583  10K_1%_2  [R0201]  82.72 97.43 90 top
R586  10K_1%_2  [R0201]  82.72 98.45 270 top
R588  *0_5%_4  [R0402]  23.55 25.17 135 top
R589  *0_5%_4  [R0402]  17.55 17.37 135 top
R592  *0_5%_2  [R0201]  82.47 94.89 270 top
R593  *0_2/S  [S0201]  84.48 100.99 270 top
R600  *1.2K_5%_2  [R0201]  92.38 97.81 180 top
R601  *0_2/S  [S0201]  87.73 102 180 top
R608  *0_5%_4  [R0402]  114.85 110.26 0 bottom
R609  10K_1%_2  [R0201]  112.82 104.75 180 bottom
R614  *Short_0603  [S0603]  119.17 99.26 90 bottom
R646  *SSD@0_2/S  [S0201]  23.67 82.57 270 bottom
R647  *SSD@0_2/S  [S0201]  24.43 82.57 270 bottom
R651  100K_1%_2  [R0201]  183.94 111.02 270 top
R652  4.7K_1%_2  [R0201]  183.94 109.88 90 top
R665  49.9_1%_2  [R0201]  194.61 116.61 270 bottom
R667  49.9_1%_2  [R0201]  194.61 115.59 0 bottom
R670  *0_4/S  [S0402]  194.99 110.77 180 bottom
R671  *10K_1%_2  [R0201]  194.48 108.48 270 bottom
R672  *10K_1%_2  [R0201]  194.48 107.34 270 bottom
R676  *75K_1%_2  [R0201]  190.67 118.64 180 top
R678  *75K_1%_2  [R0201]  186.35 119.02 180 top
R720  33_1%_2  [R0201]  195.24 98.83 90 top
R732  *100K_1%_2  [R0201]  28.87 33.55 0 bottom
R734  10K_1%_2  [R0201]  26.33 28.47 180 bottom
R735  *0_2/S  [S0201]  26.46 24.91 90 bottom
R736  *0_4/S  [S0402]  24.28 26.5 0 top
R738  *0_4/S  [S0402]  26.87 30.32 0 bottom
R752  6.2K_1%_2  [R0201]  26.72 64.67 270 bottom
R753  *Short_0603  [S0603]  27.1 67.59 90 bottom
R803  CRT@75_1%_2  [R0201]  25.24 151.09 180 top
R821  1K_1%_2  [R0201]  107.11 106.32 270 top
R822  1K_1%_2  [R0201]  107.49 103.15 90 top
R825  *100K_1%_2  [R0201]  111.3 108.61 270 top
R849  CRT@75_1%_2  [R0201]  24.03 152.66 270 top
R850  CRT@75_1%_2  [R0201]  23.48 154.54 90 top
R890  100K_1%_2  [R0201]  149.27 96.03 180 top
R894  *0_2/S  [S0201]  148.31 100.28 90 top
R895  33_1%_2  [R0201]  169.59 113.18 0 top
R953  1K_1%_2  [R0201]  77.52 96.03 90 top
R956  33_1%_2  [R0201]  170.96 103.17 270 top
R960  33_1%_2  [R0201]  169.31 104.95 90 top
R971  20K_1%_2  [R0201]  77.39 104.54 90 top
R978  *0_4/S  [S0402]  78.53 96.29 270 top
R979  20K_1%_2  [R0201]  79.17 101.24 90 top
R1234  HDD@4.7K_1%_2  [R0201]  233.85 116.35 180 top
R1235  HDD@4.7K_1%_2  [R0201]  226.69 114.8 0 top
R1236  *HDD@4.7K_1%_2  [R0201]  226.69 116.68 0 top
R1237  HDD@4.7K_1%_2  [R0201]  225.17 117.67 180 top
R1238  HDD@4.7K_1%_2  [R0201]  225.17 116.68 180 top
R1239  *HDD@Short_0603  [S0603]  235.25 118.89 90 top
R1250  20K_1%_2  [R0201]  16.3 134.72 0 bottom
R1616  *CRT@4.7K_1%_2  [R0201]  30.78 148.1 90 top
R1684  *10K_1%_2  [R0201]  57.65 136.32 180 top
R2652  *SSD@0_2/S  [S0201]  34.19 82.57 270 bottom
R2653  *SSD@0_2/S  [S0201]  33.43 82.57 270 bottom
R2654  *SSD@0_2/S  [S0201]  30.66 82.55 270 bottom
R2655  *SSD@0_2/S  [S0201]  29.9 82.55 270 bottom
R2656  *SSD@0_2/S  [S0201]  27.49 82.55 270 bottom
R2657  *SSD@0_2/S  [S0201]  26.75 82.55 270 bottom
R2658  *SSD@0_2/S  [S0201]  21.49 82.5 270 bottom
R2659  *SSD@0_2/S  [S0201]  20.73 82.5 270 bottom
R2661  *SSD@Short_0603  [S0603]  29.26 70.25 0 bottom
R2665  *0_2/S  [S0201]  194.86 109.5 0 bottom
R2666  *0_5%_8  [R0805]  196.39 120.04 90 bottom
R2667  *Short_0603  [S0603]  194.36 120.04 90 bottom
R4008  I219@1K_1%_2  [R0201]  14.02 166.9 180 top
R4009  I219@3.01K_1%_2  [R0201]  26.21 171.47 0 top
R4023  I219@499_1%_2  [R0201]  15.03 168.81 0 top
R4024  I219@499_1%_2  [R0201]  14 165.99 0 top
R9340  I219@4.7K_1%_2  [R0201]  29 158.65 0 top
R25270  *100K_1%_2  [R0201]  67.94 191.03 270 top
R25271  *100K_1%_2  [R0201]  67.13 191.03 270 top
R25282  EV@1.33K_1%_2  [R0201]  158.64 193.85 180 top
R25283  EV@931_1%_2  [R0201]  160.42 192.53 0 top
R25284  EV@549_1%_2  [R0201]  160.42 193.8 180 top
R25288  *Short_0402  [S0402]  59.99 189.89 270 bottom
R25289  *Short_0402  [S0402]  61.01 189.89 270 bottom
R25295  *Short_0402  [S0402]  114.85 105.05 180 top
R25297  *0_4/S  [S0402]  16.52 132.81 0 bottom
R25298  100K_1%_2  [R0201]  144.44 97.3 90 top
R25300  100K_1%_2  [R0201]  145.33 101.67 180 top
R25303  *10K_1%_2  [R0201]  165.73 113.43 90 top
R25304  4.7K_1%_2  [R0201]  146.12 108.3 0 top
R25306  2.2_5%_6  [R0603]  170.43 109.98 90 top
R25307  *2.2_5%_6  [R0603]  144.8 106.4 90 top
R25308  33_1%_2  [R0201]  149.65 110.92 90 top
R25309  10K_1%_2  [R0201]  167 113.18 90 top
R25310  100K_1%_2  [R0201]  69.13 181 90 bottom
R25311  100K_1%_2  [R0201]  170.35 97.43 90 top
R25312  10K_1%_2  [R0201]  144.32 100.61 90 top
R25314  10K_1%_2  [R0201]  162.81 113.18 90 top
R25315  33_1%_2  [R0201]  162.28 115.47 90 top
R25316  *10K_1%_2  [R0201]  164.99 113.43 90 top
R25317  2.2_5%_6  [R0603]  146.22 106.4 90 top
R25318  33_1%_2  [R0201]  169.08 95.02 0 top
R25320  100K_1%_2  [R0201]  155.2 113.05 90 top
R25321  *Short_0402  [S0402]  14.14 155.6 0 bottom
R25322  EV@10K_1%_2  [R0201]  129.51 175.41 90 bottom
R25323  *10K_1%_2  [R0201]  148.89 110.92 270 top
R25330  *0_4/S  [S0402]  167.94 115.08 90 top
R25344  *Short_0603  [S0603]  94.79 99.97 270 top
R25346  *0_5%_6  [R0603]  94.79 102.64 90 top
R25347  *Short_0603  [S0603]  94.84 96.68 270 top
R25348  *0_5%_6  [R0603]  96.37 96.68 270 top
R25365  *0_4/S  [S0402]  84.17 188.9 0 bottom
R25366  *0_4/S  [S0402]  84.02 191.13 180 bottom
R25367  10K_1%_2  [R0201]  82.21 192.3 0 bottom
R25368  10K_1%_2  [R0201]  88.69 189.38 0 bottom
R25369  100K_1%_2  [R0201]  83.87 190.01 180 bottom
R25370  *100K_1%_2  [R0201]  88.69 190.4 180 bottom
R25371  22K_5%_2  [R0201]  26.46 26.18 270 bottom
R25372  10K_1%_2  [R0201]  182.42 121.18 270 bottom
R25373  10K_1%_2  [R0201]  168.83 123.47 90 bottom
R25445  10K_1%_2  [R0201]  23.41 160.55 0 top
R25446  *0_5%_4  [R0402]  23.41 159.28 270 top
R25456  *0_5%_6  [R0603]  75.26 192.5 180 top
R25458  *Short_0603  [S0603]  76.07 190.83 0 top
R25459  *Short_0603  [S0603]  72.56 190.67 270 bottom
R25462  *Short_0603  [S0603]  71.8 190.65 270 top
R25467  33_1%_2  [R0201]  67.48 188.26 0 top
R25468  *EV@Short_0201  [S0201]  111.68 179.35 90 top
R25469  *EV@0_4/S  [S0402]  127.17 208.56 90 bottom
R25473  *0_4/S  [S0402]  135.17 103.2 180 bottom
R25482  *EV@10K_1%_2  [R0201]  110.41 182.14 0 top
R25487  *EV@0_5%_4  [R0402]  114.6 188.46 270 bottom
R25488  EV@80.6_1%_2  [R0201]  160.8 186.69 180 bottom
R25489  EV@80.6_1%_2  [R0201]  160.16 191.77 180 bottom
R25490  EV@10K_1%_2  [R0201]  113.96 184.17 270 top
R25492  *EV@10K_1%_2  [R0201]  119.4 177.64 270 bottom
R25495  *0_4/S  [S0402]  28.62 32.66 0 bottom
R25517  *0_4/S  [S0402]  20.49 88.67 180 top
R25518  *0_4/S  [S0402]  20.49 87.65 180 top
R25519  2.2_5%_6  [R0603]  151.18 209.32 180 top
R25524  *0_5%_4  [R0402]  140 98.07 270 top
R25526  CRT@4.7K_1%_2  [R0201]  33.07 156.49 90 top
R25527  CRT@4.7K_1%_2  [R0201]  32.18 156.49 90 top
R25528  CRT@2.2K_5%_2  [R0201]  13.38 157.25 90 top
R25529  CRT@2.2K_5%_2  [R0201]  10.08 160.8 270 top
R25530  *CRT@0_5%_4  [R0402]  32.81 148.1 90 top
R25531  *CRT@0_5%_4  [R0402]  33.83 148.1 90 top
R25532  CRT@47_1%_2  [R0201]  15.79 158.26 0 top
R25533  *CRT@4.7K_1%_2  [R0201]  33.32 146.33 90 top
R25534  CRT@100K_1%_2  [R0201]  34.59 146.33 270 top
R25535  CRT@47_1%_2  [R0201]  20.11 158.39 0 top
R25554  SM@4.7K_1%_2  [R0201]  224.71 94.13 90 top
R25555  SM@100K_1%_2  [R0201]  211 96.69 0 top
R25556  *SM@0_5%_4  [R0402]  211 94.73 180 top
R25557  *SM@0_5%_4  [R0402]  210.97 93.68 0 top
R25558  SM@470_1%_2  [R0201]  223.95 94.13 270 top
R25559  *SM@0_4/S  [S0402]  223.26 96.03 0 top
R25560  *SM@0_4/S  [S0402]  223.26 97.02 0 top
R25596  *0_5%_4  [R0402]  53.09 105.5 180 top
R25597  *0_4/S  [S0402]  53.04 104.47 0 top
R25598  *0_5%_4  [R0402]  56.31 130.32 180 top
R25599  *0_4/S  [S0402]  54.39 104.14 270 top
R25600  *0_5%_4  [R0402]  58.76 103.53 180 top
R25601  *0_4/S  [S0402]  57.7 129.94 270 top
R25602  *240_1%_2  [R0201]  57.7 149.25 270 top
R25603  *240_1%_2  [R0201]  65.83 149.12 0 top
R25604  *240_1%_2  [R0201]  65.76 145.95 0 top
R25605  *240_1%_2  [R0201]  68.24 145.06 90 top
R25606  *240_1%_2  [R0201]  60.24 149.25 270 top
R25607  240_1%_2  [R0201]  65.7 147.72 0 top
R25608  *240_1%_2  [R0201]  65.83 150.77 0 top
R25609  *240_1%_2  [R0201]  54.15 147.09 90 top
R25610  *240_1%_2  [R0201]  56.59 146.2 180 top
R25611  240_1%_2  [R0201]  68.88 147.72 180 top
R25612  1K_1%_2  [R0201]  57.09 125.96 180 top
R25614  24.9_1%_2  [R0201]  55.62 120.98 0 top
R25615  1K_1%_2  [R0201]  57.09 126.79 0 top
R25617  *Short_0805  [S0805]  26.21 176.68 0 top
R25618  *0_5%_8  [R0805]  23.54 177.31 270 top
R25619  100K_1%_2  [R0201]  32.18 173.38 90 top
R25620  10K_1%_2  [R0201]  32.3 174.77 180 top
R25622  *SPIN@Short_0603  [S0603]  135.43 216.18 180 top
R25623  SPIN@0_5%_2  [R0201]  141.78 209.83 90 top
R25624  *SPIN@0_5%_2  [R0201]  141.27 211.73 180 top
R25625  *SPIN@0_5%_6  [R0603]  135.43 214.53 0 top
R25629  SPIN_EXT@4.7K_1%_2  [R0201]  106.09 175.13 180 bottom
R25630  *SPIN_EXT@0_5%_4  [R0402]  106.22 176.02 0 bottom
R25631  SPIN_EXT@4.7K_1%_2  [R0201]  104.82 176.04 180 bottom
R25632  *SPIN_EXT@0_5%_4  [R0402]  103.42 176.04 180 bottom
R25633  SPIN_EXT@100K_1%_2  [R0201]  155.11 214.4 270 bottom
R25634  SPIN_EXT@4.7K_1%_2  [R0201]  132.38 215.41 180 top
R25635  SPIN_EXT@2K_1%_2  [R0201]  158.41 214.53 270 top
R25636  SPIN_EXT@2K_1%_2  [R0201]  151.94 216.68 90 bottom
R25637  SPIN_EXT@0_5%_4  [R0402]  158.54 213.19 180 top
R25638  SPIN_EXT@0_5%_4  [R0402]  151.05 216.56 270 bottom
R25639  *SPIN_EXT@0_5%_4  [R0402]  131.17 216.11 270 top
R25641  SPIN_EXT@0_5%_4  [R0402]  150.16 213.89 180 bottom
R67358  *HDD@0_4/S  [S0402]  221.73 104.75 0 top
R67359  *HDD@Short_0603  [S0603]  224.71 108.86 180 top
R67360  4.7K_1%_2  [R0201]  9.29 13.51 180 top
R67361  68.1K_1%_2  [R0201]  9.57 12.52 180 top
R67362  150K_5%_2  [R0201]  7.54 12.13 0 top
R67367  P2_P2SPIN@0_5%_6  [R0603]  48.94 93.15 90 top
R67368  P2_P2SPIN@0_5%_6  [R0603]  45.28 93.06 90 top
R67369  P2_P2SPIN@0_5%_6  [R0603]  42.31 93.04 90 top
R67370  P2_P2SPIN@0_5%_6  [R0603]  39.36 93.04 90 top
R67414  *Short_0402  [S0402]  58.59 189.89 270 bottom
R67415  *Short_0402  [S0402]  57.58 189.89 270 bottom
R67422  *0_5%_2  [R0201]  201.72 122.7 180 bottom
R67447  *Short_0402  [S0402]  144.57 108.61 0 top
R67448  *Short_0402  [S0402]  144.57 109.62 0 top
R67461  P2_P2SPIN@0_5%_4  [R0402]  208.77 115.89 270 bottom
R67462  P2_P2SPIN@0_5%_4  [R0402]  207.77 115.89 270 bottom
R67474  10K_1%_2  [R0201]  29.38 165 270 top
R67475  *8111K@0_5%_4  [R0402]  29.38 166.39 270 top
R67476  8111K@0_5%_4  [R0402]  28.37 166.39 270 top
R67477  8111K@2.49K_1%_2  [R0201]  26.21 170.76 180 top
R67484  100K_1%_2  [R0201]  149.14 99.21 270 top
R67485  100K_1%_2  [R0201]  149.86 99.18 270 top
R67486  100K_1%_2  [R0201]  148.05 97.53 180 top
R67487  100K_1%_2  [R0201]  149.14 96.97 180 top
R67492  SPIN_N@0_5%_4  [R0402]  94.79 101.19 0 bottom
R67493  SPIN_N@0_5%_4  [R0402]  94.79 100 0 bottom
R67496  SPIN@0_5%_4  [R0402]  95.57 100 0 bottom
R67497  SPIN@0_5%_4  [R0402]  95.57 101.19 0 bottom
R67504  *I219@0_5%_4  [R0402]  29.38 163.98 180 top
R67505  I219@0_5%_4  [R0402]  27.1 162.33 270 top
R67506  8111K@0_5%_4  [R0402]  25.93 162.33 270 top
R67507  I219@0_5%_4  [R0402]  33.83 175.34 270 top
R67508  8111K@0_5%_4  [R0402]  32.73 176.07 90 top
R67509  *I219@10K_1%_2  [R0201]  16.68 166.39 270 bottom
R67510  *I219@10K_1%_2  [R0201]  15.03 163.73 0 top
R67511  *I219@10K_1%_2  [R0201]  15.03 164.61 0 top
R67512  *I219@10K_1%_2  [R0201]  15.03 162.84 0 top
R67513  I219@0_5%_4  [R0402]  27.35 166.39 90 top
R67514  2_1%_6  [R0603]  56.94 123.67 270 top
R67524  *I219@10K_1%_2  [R0201]  27.99 164.11 270 top
R67525  *I219@0_5%_4  [R0402]  12.75 169.06 180 top
R67526  *I219@0_5%_4  [R0402]  11.6 165.5 180 top
R67532  22_5%_2  [R0201]  33.07 46.76 90 bottom
R67539  *0_4/S  [S0402]  32.05 54.38 270 bottom
R67551  *Short_0603  [S0603]  77.9 190.93 0 bottom
R67555  *NFC@10K_1%_2  [R0201]  59.23 96.29 180 top
R67556  *NFC@3.3K_5%_2  [R0201]  69.26 96.16 180 top
R67557  *NFC@3.3K_5%_2  [R0201]  60.62 96.29 180 top
R67560  *NFC@Short_0603  [S0603]  70.4 97.43 0 top
R67561  *NFC@4.7K_1%_2  [R0201]  60.24 92.86 180 top
R67562  *NFC@0_4/S  [S0402]  62.66 99.21 180 top
R67563  *NFC@4.7K_1%_2  [R0201]  67.74 92.86 0 top
R67564  *NFC@0_5%_4  [R0402]  62.15 96.54 180 top
R67565  *NFC@Short_0603  [S0603]  57.83 95.4 270 top
R67566  *NFC@0_5%_4  [R0402]  66.21 96.29 0 top
R67567  *NFC@0_5%_4  [R0402]  68.24 94.81 90 top
R67568  NFC@4.7K_1%_2  [R0201]  64.31 92.86 180 top
R67569  NFC@10K_1%_2  [R0201]  68.12 96.16 180 top
R67570  *NFC@0_5%_4  [R0402]  64.05 96.54 0 top
R67571  NFC@4.7K_1%_2  [R0201]  62.02 92.86 0 top
R67572  *NFC@3.3K_5%_2  [R0201]  66.85 97.18 180 top
R67573  *NFC@4.7K_1%_2  [R0201]  66.21 92.86 180 top
R67574  *0_5%_4  [R0402]  44.62 124.07 270 top
R67575  *0_5%_4  [R0402]  44.62 125.81 90 top
R67598  I219@0_5%_4  [R0402]  22.02 158.9 180 top
R67599  I219@0_5%_4  [R0402]  22.4 160.3 90 top
R67604  *2.2K_5%_2  [R0201]  149.65 109.88 180 top
R67606  *SM@10K_1%_2  [R0201]  210.96 92.79 0 top
R67855  *Short_0603  [S0603]  94.66 189.63 90 bottom
R67857  2.2K_5%_2  [R0201]  94.64 180.46 0 bottom
R67858  2.2K_5%_2  [R0201]  93.39 184.55 180 bottom
R67861  SPIN@0_5%_4  [R0402]  206.22 97.65 90 top
R67864  SPIN@1K_1%_2  [R0201]  139.62 210.21 180 top
R67865  10K_1%_2  [R0201]  31.29 50.06 90 bottom
R67866  *HDD@0_4/S  [S0402]  221.32 106.9 0 top
R67871  *10K_1%_2  [R0201]  171.62 104.8 270 top
R67873  *SPIN_INT@0_5%_4  [R0402]  148.04 216.2 180 top
R67875  *SPIN_INT@0_5%_4  [R0402]  148.1 214.95 0 top
R67886  *Short_0402  [S0402]  183.4 100.58 180 top
R67887  *0_4/S  [S0402]  33.07 54.38 90 bottom
R67888  10K_1%_2  [R0201]  32.05 50.06 90 bottom
R67895  22_5%_2  [R0201]  32.81 35.2 90 bottom
R67896  22_5%_2  [R0201]  32.81 38.25 270 bottom
R67897  22_5%_2  [R0201]  33.07 49.93 90 bottom
R67898  22_5%_2  [R0201]  33.07 52.98 270 bottom
R67899  22_5%_2  [R0201]  32.81 39.27 90 bottom
R68199  4.7K_1%_2  [R0201]  28.11 130.58 0 top
R68200  *0_5%_4  [R0402]  28.6 120.44 270 top
R68201  *0_5%_4  [R0402]  27.58 120.44 270 top
R68202  4.99K_1%_2  [R0201]  30.53 120.93 270 top
R68203  *4.7K_1%_2  [R0201]  25.95 120.93 90 top
R68204  *4.7K_1%_2  [R0201]  26.67 120.93 90 top
R68210  *4.7K_1%_2  [R0201]  27.1 131.47 180 top
R68211  *4.7K_1%_2  [R0201]  27.1 130.58 0 top
R68215  *4.7K_1%_2  [R0201]  22.65 120.8 270 top
R68216  10K_1%_2  [R0201]  29.64 120.29 180 top
R68217  *10K_1%_2  [R0201]  24.07 120.75 90 top
R68218  *10K_1%_2  [R0201]  23.36 120.75 90 top
R68219  *10K_1%_2  [R0201]  31.54 120.93 270 top
R68221  *Short_0402  [S0402]  32.56 120.55 270 top
R68227  100K_1%_2  [R0201]  90.98 123.97 270 top
R68228  *Short_0402  [S0402]  18.84 120.8 0 top
R68229  *Short_0402  [S0402]  18.84 121.82 0 top
R68230  *Short_0402  [S0402]  18.84 122.83 0 top
R68231  *Short_0402  [S0402]  18.84 123.85 0 top
R68232  *Short_0402  [S0402]  18.84 125.88 0 top
R68233  *Short_0402  [S0402]  18.84 126.9 0 top
R68236  *Short_0603  [S0603]  25.75 133.19 90 top
R68237  *Short_0402  [S0402]  29.64 133.25 0 top
R68242  150_1%_2  [R0201]  127.43 151.03 90 bottom
R68243  100K_1%_2  [R0201]  123.49 122.32 180 top
R68245  150_1%_2  [R0201]  128.52 154.84 0 bottom
R68246  100K_1%_2  [R0201]  131.11 162.84 90 top
R68247  *10K_1%_2  [R0201]  90.98 125.02 270 top
R68248  10K_1%_2  [R0201]  91.74 125.02 270 top
R68249  100_1%_2  [R0201]  103.47 163.78 0 top
R68250  10K_1%_2  [R0201]  83.23 172.11 180 top
R68251  *10K_1%_2  [R0201]  86.02 170.84 270 top
R68252  470_1%_2  [R0201]  92.25 118.89 0 top
R68253  *Short_0201  [S0201]  92.25 118.13 180 top
R68254  10K_1%_2  [R0201]  90.98 167.79 180 top
R68255  100K_1%_2  [R0201]  88.64 169.19 90 top
R68256  100K_1%_2  [R0201]  91.99 167.79 180 top
R68257  1K_1%_2  [R0201]  130.22 162.84 270 top
R68259  1K_1%_2  [R0201]  124.76 172.49 90 bottom
R68260  499_1%_2  [R0201]  125.52 170.08 0 bottom
R68261  *51_1%_2  [R0201]  120.06 172.49 90 bottom
R68262  49.9_1%_2  [R0201]  107.95 132.76 270 top
R68263  51_1%_2  [R0201]  117.27 171.73 90 bottom
R68264  49.9_1%_2  [R0201]  130.73 135.79 180 top
R68265  *Short_0201  [S0201]  121.08 170.2 0 bottom
R68266  *51_1%_2  [R0201]  118.16 172.62 180 bottom
R68267  *Short_0201  [S0201]  119.98 170.2 180 bottom
R68268  *Short_0201  [S0201]  117.22 170.02 0 bottom
R68269  *Short_0201  [S0201]  118.16 171.85 180 bottom
R68270  *51_1%_2  [R0201]  119.3 172.49 90 bottom
R68271  *Short_0201  [S0201]  125.01 162.23 180 top
R68274  51_1%_2  [R0201]  121.58 172.49 90 bottom
R68275  *51_1%_2  [R0201]  126.03 162.23 0 top
R68276  *51_1%_2  [R0201]  120.82 172.49 90 bottom
R68277  1K_1%_2  [R0201]  127.93 168.3 0 bottom
R68278  *10K_1%_2  [R0201]  123.24 116.35 90 bottom
R68279  *1K_1%_2  [R0201]  127.93 167.41 180 bottom
R68280  *Short_0402  [S0402]  121.33 167.69 270 top
R68281  *Short_0402  [S0402]  134.97 154.02 270 top
R68282  *Short_0402  [S0402]  132.81 155.01 180 top
R68283  56.2_1%_2  [R0201]  119.3 171.6 270 top
R68284  100_1%_2  [R0201]  117.77 171.6 270 top
R68285  *Short_0201  [S0201]  120.06 171.6 90 top
R68286  *Short_0201  [S0201]  121.46 171.09 90 top
R68287  *Short_0201  [S0201]  118.54 171.6 90 top
R68290  200_1%_2  [R0201]  94.53 120.09 180 bottom
R68291  *1K_1%_2  [R0201]  123.74 169.19 90 bottom
R68292  1K_1%_2  [R0201]  127.93 168.68 180 top
R68293  1K_1%_2  [R0201]  127.93 167.92 180 top
R68294  1K_1%_2  [R0201]  127.93 164.87 180 top
R68295  *1K_1%_2  [R0201]  127.93 166.01 180 top
R68296  *1K_1%_2  [R0201]  124.25 168.93 270 top
R68297  *1K_1%_2  [R0201]  127.93 163.22 180 top
R68298  1K_1%_2  [R0201]  127.93 166.77 180 top
R68299  *1K_1%_2  [R0201]  127.93 162.46 180 top
R68300  1K_1%_2  [R0201]  117.14 169.57 270 top
R68301  1K_1%_2  [R0201]  127.93 164.11 180 top
R68302  1K_1%_2  [R0201]  117.9 169.57 270 top
R68303  *1K_1%_2  [R0201]  122.35 168.93 270 top
R68304  *1K_1%_2  [R0201]  127.93 161.69 180 top
R68305  49.9_1%_2  [R0201]  122.47 172.49 90 bottom
R68306  1K_1%_2  [R0201]  119.04 169.57 270 top
R68307  *1K_1%_2  [R0201]  119.81 169.57 270 top
R68308  10K_1%_2  [R0201]  127.3 157.38 180 bottom
R68309  10K_1%_2  [R0201]  127.3 155.85 180 bottom
R68310  10K_1%_2  [R0201]  129.46 162.84 270 top
R68311  10K_1%_2  [R0201]  127.3 156.61 180 bottom
R68312  *51_1%_2  [R0201]  123.11 167.54 90 top
R68313  2.2K_5%_2  [R0201]  127.43 149.25 90 bottom
R68314  *10K_1%_2  [R0201]  93.64 163.85 180 bottom
R68317  *1K_1%_2  [R0201]  117.9 168.04 270 top
R68320  *1K_1%_2  [R0201]  122.35 167.54 270 top
R68321  *1K_1%_2  [R0201]  123.74 160.93 0 top
R68322  *1K_1%_2  [R0201]  117.17 168.04 270 top
R68323  *Short_0201  [S0201]  122.85 169.19 90 bottom
R68324  *1K_1%_2  [R0201]  123.62 171.47 180 bottom
R68325  *1K_1%_2  [R0201]  126.03 167.92 0 top
R68326  1K_1%_2  [R0201]  126.03 166.01 0 top
R68327  *1K_1%_2  [R0201]  126.03 166.77 0 top
R68328  *1K_1%_2  [R0201]  126.03 164.11 0 top
R68329  *1K_1%_2  [R0201]  119.04 168.04 270 top
R68330  *1K_1%_2  [R0201]  119.76 168.04 270 top
R68331  *1K_1%_2  [R0201]  126.03 168.68 0 top
R68332  *1K_1%_2  [R0201]  126.03 164.87 0 top
R68333  *1K_1%_2  [R0201]  124.23 167.03 270 top
R68334  *1K_1%_2  [R0201]  126.03 162.96 0 top
R68335  *1K_1%_2  [R0201]  126.92 161.95 90 top
R68336  100K_1%_2  [R0201]  121.58 110.39 270 top
R68339  49.9_1%_2  [R0201]  97.18 122.2 270 bottom
R68340  15_1%_2  [R0201]  95.68 123.85 270 bottom
R68341  15_1%_2  [R0201]  96.95 124.28 180 bottom
R68342  15_1%_2  [R0201]  96.95 121.33 180 bottom
R68343  15_1%_2  [R0201]  94.53 121.03 180 bottom
R68344  *Short_0201  [S0201]  96.95 123.57 180 bottom
R68345  *Short_0201  [S0201]  95.17 122.02 270 bottom
R68346  *1K_1%_2  [R0201]  116.38 117.62 270 top
R68347  *1K_1%_2  [R0201]  117.14 117.62 270 top
R68348  499_1%_2  [R0201]  73.45 97.18 0 top
R68349  499_1%_2  [R0201]  72.56 97.05 270 top
R68350  2.2K_5%_2  [R0201]  128.82 112.8 90 bottom
R68351  2.2K_5%_2  [R0201]  129.59 112.8 90 bottom
R68352  EV@100K_1%_2  [R0201]  121.58 125.24 180 top
R68353  75K_1%_2  [R0201]  93.19 122.45 270 bottom
R68354  100K_1%_2  [R0201]  93.19 121.46 270 bottom
R68355  10K_1%_2  [R0201]  120.06 115.08 90 bottom
R68356  EV@10K_1%_2  [R0201]  127.05 116.23 90 top
R68357  *EV@10K_1%_2  [R0201]  124.89 123.8 90 top
R68358  *EV@10K_1%_2  [R0201]  121.84 116.23 90 bottom
R68359  10K_1%_2  [R0201]  124.12 123.8 90 top
R68360  *Short_0201  [S0201]  76.25 119.91 90 top
R68361  4.7K_1%_2  [R0201]  76.25 118.26 270 top
R68362  *Short_0201  [S0201]  79.55 119.91 270 top
R68363  4.7K_1%_2  [R0201]  79.8 118.39 270 top
R68364  *4.7K_1%_2  [R0201]  93.87 125.88 90 bottom
R68365  *4.7K_1%_2  [R0201]  121.08 113.18 0 bottom
R68366  *4.7K_1%_2  [R0201]  124.91 126.64 90 top
R68367  4.7K_1%_2  [R0201]  114.47 117.37 90 top
R68368  *4.7K_1%_2  [R0201]  118.13 116.74 270 bottom
R68369  100K_1%_2  [R0201]  121.97 112.93 0 top
R68370  *Short_0201  [S0201]  121.97 112.16 0 top
R68371  *20K_1%_2  [R0201]  94.74 126.08 270 bottom
R68372  *20K_1%_2  [R0201]  122.09 113.18 0 bottom
R68373  *20K_1%_2  [R0201]  125.78 126.95 0 top
R68374  *20K_1%_2  [R0201]  113.69 117.37 270 top
R68375  *20K_1%_2  [R0201]  117.65 115.21 270 top
R68376  *4.7K_1%_2  [R0201]  123.49 113.31 90 top
R68377  4.7K_1%_2  [R0201]  94.91 128.01 0 bottom
R68378  100K_1%_2  [R0201]  123.11 110.39 270 top
R68379  100K_1%_2  [R0201]  129.97 126.9 180 top
R68380  100K_1%_2  [R0201]  119.93 110.51 0 top
R68381  *Short_0201  [S0201]  120.82 110.44 270 top
R68382  *150K_5%_2  [R0201]  95.17 128.8 0 bottom
R68383  *20K_1%_2  [R0201]  95.91 127.66 270 bottom
R68384  *4.7K_1%_2  [R0201]  122.35 110.39 270 top
R68385  *4.7K_1%_2  [R0201]  130.98 126.13 0 top
R68386  *4.7K_1%_2  [R0201]  119.65 109.52 270 top
R68387  *20K_1%_2  [R0201]  96.18 128.8 0 bottom
R68388  vpro@4.7K_1%_2  [R0201]  118.41 115.21 270 top
R68389  *4.7K_1%_2  [R0201]  118.41 113.18 90 top
R68390  100K_1%_2  [R0201]  118.28 113.43 270 bottom
R68391  *100K_1%_2  [R0201]  117.52 113.43 270 bottom
R68392  4.7K_1%_2  [R0201]  107.59 108.78 90 bottom
R68395  *20K_1%_2  [R0201]  118.41 114.2 270 top
R68396  *4.7K_1%_2  [R0201]  118.28 114.45 90 bottom
R68400  1K_1%_2  [R0201]  128.82 126.13 90 bottom
R68401  1M_1%_2  [R0201]  107.36 109.62 90 top
R68405  *20K_1%_2  [R0201]  127.43 125.12 0 bottom
R68406  *1M_1%_2  [R0201]  106.73 111.27 0 top
R68408  *4.7K_1%_2  [R0201]  104.95 111.4 0 bottom
R68409  *4.7K_1%_2  [R0201]  129.71 128.04 90 top
R68410  *4.7K_1%_2  [R0201]  101.01 110 90 bottom
R68411  *20K_1%_2  [R0201]  104.95 112.16 180 bottom
R68412  *20K_1%_2  [R0201]  128.49 128.04 270 top
R68413  4.7K_1%_2  [R0201]  101.75 118.31 0 bottom
R68418  10K_1%_2  [R0201]  125.78 125.37 90 top
R68419  10K_1%_2  [R0201]  92.5 125.02 90 top
R68420  10K_1%_2  [R0201]  110.18 114.72 0 bottom
R68421  100_1%_2  [R0201]  121.58 118.26 180 bottom
R68422  10K_1%_2  [R0201]  122.6 128.55 180 top
R68423  10K_1%_2  [R0201]  127.43 125.88 180 bottom
R68424  113_1%_2  [R0201]  127.81 126.9 0 bottom
R68426  2.2K_1%_2  [R0201]  130.12 155.37 270 top
R68427  150_1%_2  [R0201]  92.37 123.97 180 top
R68428  *20K_1%_2  [R0201]  128.19 126.77 90 top
R68429  *Short_0201  [S0201]  130.98 126.9 180 top
R68430  *20K_1%_2  [R0201]  128.95 126.26 270 top
R68431  *Short_0201  [S0201]  129.71 129.05 90 top
R68432  150_1%_2  [R0201]  117.17 166.77 270 top
R68433  *Short_0201  [S0201]  102.53 117.45 270 bottom
R68434  10M_5%_2  [R0201]  102.97 118.31 0 bottom
R68435  *Short_0201  [S0201]  104.57 115.85 0 bottom
R68436  10K_1%_2  [R0201]  111.3 113.43 270 bottom
R68437  10K_1%_2  [R0201]  112.19 111.02 0 bottom
R68438  *Short_0201  [S0201]  103.42 117.45 270 bottom
R68439  *10K_1%_2  [R0201]  115.36 117.14 0 top
R68440  10K_1%_2  [R0201]  110.49 113.43 270 bottom
R68441  10K_1%_2  [R0201]  111.17 114.96 90 bottom
R68442  *10K_1%_2  [R0201]  115.36 117.88 0 top
R68443  60.4_1%_2  [R0201]  122.52 126.34 90 top
R68444  *Short_0201  [S0201]  127.9 123.65 180 bottom
R68446  200K_1%_2  [R0201]  126.91 123.4 270 bottom
R68447  *Short_0201  [S0201]  127.9 122.89 180 bottom
R68451  33_1%_2  [R0201]  105.46 117.88 180 bottom
R68452  33_1%_2  [R0201]  107.64 118.28 180 bottom
R68453  33_1%_2  [R0201]  106.47 117.88 0 bottom
R68454  33_1%_2  [R0201]  104.44 117.37 180 bottom
R68455  *100K_1%_2  [R0201]  104.44 118.13 180 bottom
R68458  200_1%_2  [R0201]  109.01 131.72 180 top
R68459  *8.2K_1%_2  [R0201]  90.6 122.2 180 top
R68460  8.2K_1%_2  [R0201]  89.96 123.72 180 top
R68461  *10K_1%_2  [R0201]  111.17 112.67 180 top
R68463  1K_1%_2  [R0201]  115.36 113.56 90 top
R68466  *0_5%_2  [R0201]  109.82 109.62 270 top
R68467  *0_5%_2  [R0201]  108.83 109.62 270 top
R68468  *100K_1%_2  [R0201]  111.17 115.08 90 top
R68469  10K_1%_2  [R0201]  126.54 128.17 180 top
R68470  100K_1%_2  [R0201]  85.26 120.67 0 top
R68471  *10K_1%_2  [R0201]  111.04 111.27 90 top
R68472  10K_1%_2  [R0201]  94.41 122.07 90 bottom
R68473  100K_1%_2  [R0201]  91.36 120.67 90 top
R68474  100K_1%_2  [R0201]  98.75 107.59 270 top
R68475  100K_1%_2  [R0201]  100.76 118.31 0 bottom
R68476  *0_5%_2  [R0201]  85.26 119.91 0 top
R68477  75K_1%_2  [R0201]  92.5 126.01 90 top
R68478  *Short_0201  [S0201]  127.81 117.12 270 top
R68479  *Short_0201  [S0201]  84.25 120.04 0 top
R68480  *10K_1%_2  [R0201]  120.67 143.46 180 top
R68481  *1M_1%_2  [R0201]  82.85 119.15 180 top
R68482  100K_1%_2  [R0201]  83.87 121.05 90 top
R68483  100K_1%_2  [R0201]  104.57 129.18 180 top
R68484  100K_1%_2  [R0201]  127.05 117.24 90 top
R68485  *100K_1%_2  [R0201]  94.89 125.22 180 bottom
R68486  100K_1%_2  [R0201]  95.78 125.9 90 bottom
R68487  15K_1%_2  [R0201]  88.03 105.31 90 top
R68488  *15K_1%_2  [R0201]  86.74 105.31 90 top
R68489  100K_1%_2  [R0201]  90.29 105.31 90 top
